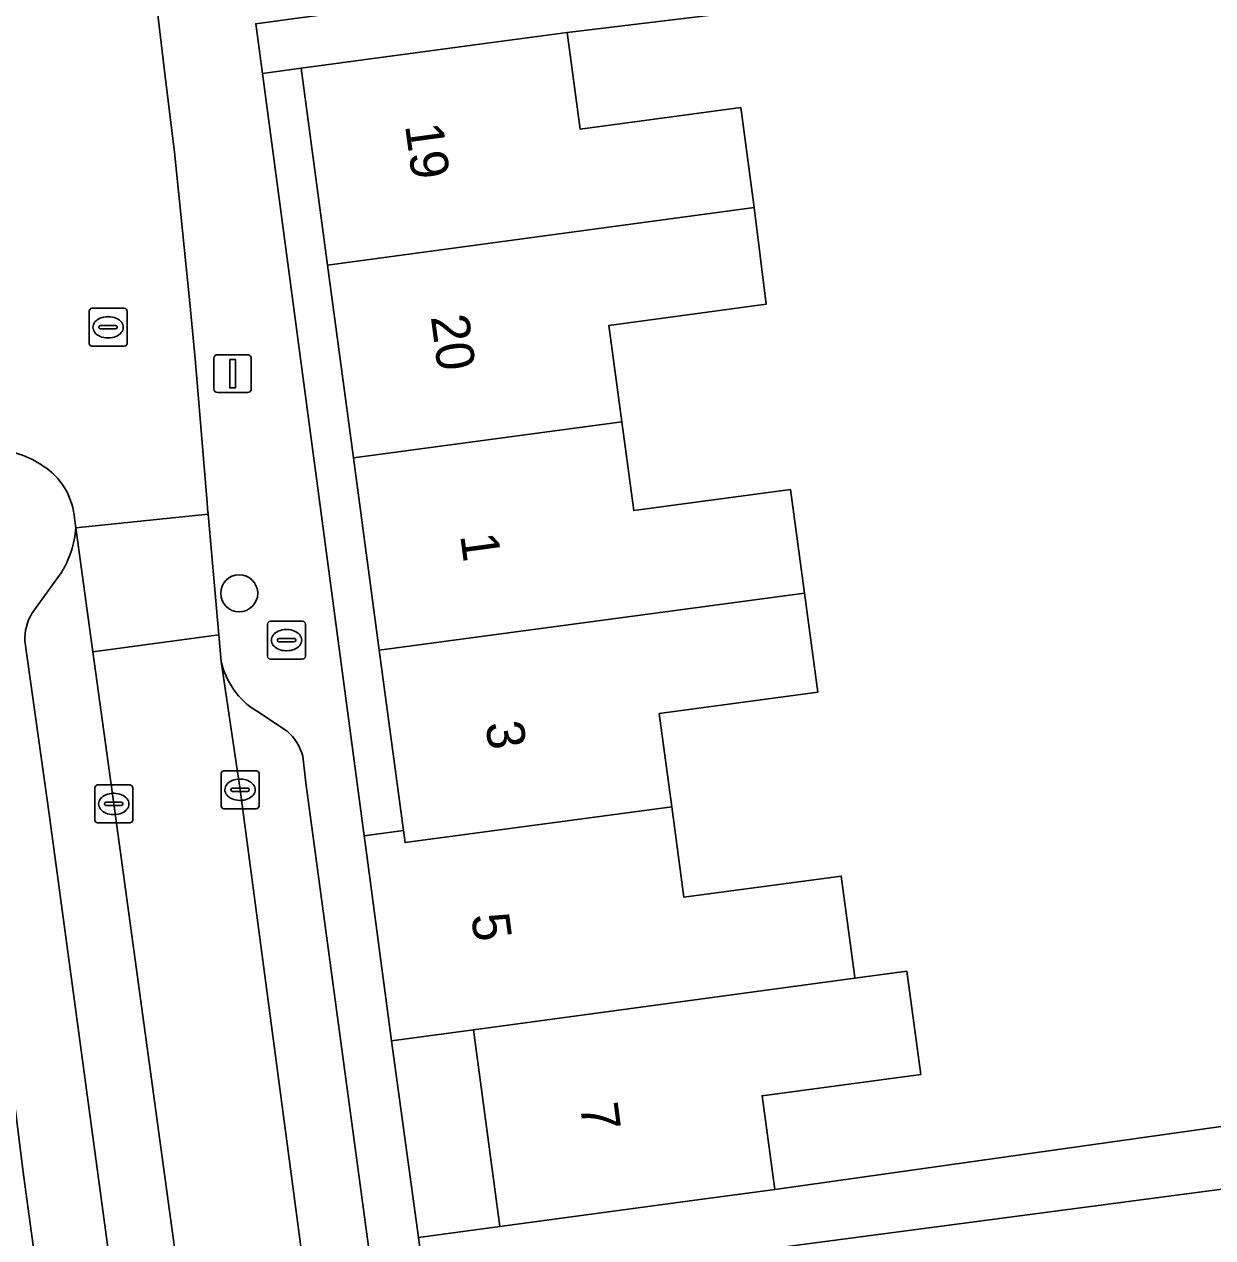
# Model space of a CAD drawing. Extents: x 163147 to 163550, y 380933 to 381639.
# Drawn here: x 163431.91 to 163463.29, y 381151.62 to 381183.65 of the extents above; entities that cross this region are included whole.
import ezdxf

# ---------------------------------------------------------------- set-up
doc = ezdxf.new("R2010")
doc.units = 0
for name, color, linetype in [('IMGEO_Boom', 7, 'Continuous'), ('IMGEO_Brandkraan', 7, 'Continuous'), ('IMGEO_Erf', 7, 'Continuous'), ('IMGEO_Kolk', 7, 'Continuous'), ('IMGEO_Lichtmast', 7, 'Continuous'), ('IMGEO_Pand', 7, 'Continuous'), ('IMGEO_Pand_nummerreeks', 7, 'Continuous'), ('IMGEO_Parkeervlak_open', 7, 'Continuous'), ('IMGEO_Rijbaan_lokaal_open', 7, 'Continuous'), ('IMGEO_Rioolput', 7, 'Continuous'), ('IMGEO_Voetpad_open', 7, 'Continuous')]:
    doc.layers.add(name, color=color, linetype=linetype)

msp = doc.modelspace()

# ---------------------------------------------------------------- linework, layer by layer
at = {"layer": 'IMGEO_Boom'}
msp.add_circle((163437.586, 381168.632), 0.489, dxfattribs=at)
at = {"layer": 'IMGEO_Brandkraan'}
for p, q in [((163438.335, 381166.969), (163438.335, 381167.821)), ((163438.41, 381167.895), (163439.262, 381167.895)), ((163438.823, 381167.675), (163438.848, 381167.675)), ((163439.336, 381167.821), (163439.336, 381166.969)), ((163438.594, 381167.389), (163438.594, 381167.401)), ((163439.032, 381167.352), (163438.634, 381167.352)), ((163438.637, 381167.438), (163439.035, 381167.438)), ((163439.078, 381167.401), (163439.078, 381167.389)), ((163438.846, 381167.115), (163438.821, 381167.115)), ((163439.262, 381166.895), (163438.41, 381166.895))]:
    msp.add_line(p, q, dxfattribs=at)
for points in [[(163438.335, 381166.969), (163438.335, 381167.821)], [(163438.41, 381167.895), (163439.262, 381167.895)], [(163439.336, 381167.821), (163439.336, 381166.969)], [(163439.262, 381166.895), (163438.41, 381166.895)]]:
    msp.add_lwpolyline(points, dxfattribs=at)
for centre, radius, start, end in [((163438.412, 381167.819), 0.0765, 91.552, 178.448), ((163438.412, 381167.819), 0.0765, 91.552, 178.448), ((163439.26, 381167.819), 0.0765, 1.552, 88.448), ((163439.26, 381167.819), 0.0765, 1.552, 88.448), ((163438.634, 381167.398), 0.0403, 85.8775, 175.7526), ((163438.631, 381167.388), 0.0366, 178.938, 274.7102), ((163439.035, 381167.395), 0.043, 264.8664, 352.4533), ((163439.039, 381167.4), 0.0386, 1.7309, 96.639), ((163438.412, 381166.971), 0.0765, 181.552, 268.448), ((163438.412, 381166.971), 0.0765, 181.552, 268.448), ((163439.26, 381166.971), 0.0765, 271.552, 358.448), ((163439.26, 381166.971), 0.0765, 271.552, 358.448)]:
    msp.add_arc(centre, radius, start, end, dxfattribs=at)
for centre, major_axis, ratio, start_param, end_param in [((163438.822, 381167.395), (-0.387, 0.002), 0.722429, 4.712389, 7.853982), ((163438.847, 381167.395), (-0.39, 0.002), 0.717154, 1.570796, 4.712389)]:
    msp.add_ellipse(centre, major_axis=major_axis, ratio=ratio, start_param=start_param, end_param=end_param, dxfattribs=at)
at = {"layer": 'IMGEO_Erf'}
for points in [[(163452.457, 381184.186), (163446.248, 381183.436), (163446.591, 381180.885), (163450.83, 381181.455), (163451.185, 381178.818), (163451.505, 381176.266), (163447.35, 381175.704), (163447.692, 381173.162), (163448.007, 381170.814), (163452.148, 381171.371), (163452.515, 381168.638), (163452.867, 381166.023), (163448.679, 381165.459), (163449.01, 381162.995), (163449.331, 381160.607), (163453.482, 381161.165), (163453.833, 381158.56), (163453.845, 381158.471), (163455.218, 381158.656), (163455.584, 381155.933), (163451.395, 381155.37), (163451.727, 381152.897), (163470.315, 381155.515)], [(163470.743, 381153.849), (163451.998, 381151.38)], [(163432.293, 381150.328), (163431.895, 381153.22)]]:
    msp.add_lwpolyline(points, dxfattribs=at)
for points in [[(163439.918, 381177.291), (163439.219, 381182.492), (163438.198, 381182.356), (163440.885, 381162.228), (163441.925, 381162.367), (163441.285, 381167.13), (163440.601, 381172.211)], [(163443.772, 381157.111), (163441.612, 381156.819), (163442.318, 381151.628), (163444.469, 381151.921)]]:
    msp.add_lwpolyline(points, close=True, dxfattribs=at)
at = {"layer": 'IMGEO_Kolk'}
for p, q in [((163437.108, 381163.02), (163437.108, 381163.872)), ((163437.183, 381163.946), (163438.035, 381163.946)), ((163438.109, 381163.872), (163438.109, 381163.02)), ((163433.773, 381162.646), (163433.773, 381163.498)), ((163433.848, 381163.572), (163434.7, 381163.572)), ((163434.774, 381163.498), (163434.774, 381162.646)), ((163437.41, 381163.489), (163437.808, 381163.489)), ((163437.596, 381163.726), (163437.621, 381163.726)), ((163434.261, 381163.352), (163434.286, 381163.352)), ((163437.367, 381163.44), (163437.367, 381163.452)), ((163437.805, 381163.403), (163437.407, 381163.403)), ((163437.619, 381163.166), (163437.594, 381163.166)), ((163437.851, 381163.452), (163437.851, 381163.44)), ((163434.032, 381163.066), (163434.032, 381163.078)), ((163434.47, 381163.029), (163434.072, 381163.029)), ((163434.075, 381163.115), (163434.473, 381163.115)), ((163434.516, 381163.078), (163434.516, 381163.066)), ((163438.035, 381162.946), (163437.183, 381162.946)), ((163434.7, 381162.572), (163433.848, 381162.572)), ((163434.284, 381162.792), (163434.259, 381162.792))]:
    msp.add_line(p, q, dxfattribs=at)
for points in [[(163437.108, 381163.02), (163437.108, 381163.872)], [(163437.183, 381163.946), (163438.035, 381163.946)], [(163438.109, 381163.872), (163438.109, 381163.02)], [(163433.773, 381162.646), (163433.773, 381163.498)], [(163433.848, 381163.572), (163434.7, 381163.572)], [(163434.774, 381163.498), (163434.774, 381162.646)], [(163438.035, 381162.946), (163437.183, 381162.946)], [(163434.7, 381162.572), (163433.848, 381162.572)]]:
    msp.add_lwpolyline(points, dxfattribs=at)
for centre, radius, start, end in [((163437.185, 381163.87), 0.0765, 91.552, 178.448), ((163437.185, 381163.87), 0.0765, 91.552, 178.448), ((163438.033, 381163.87), 0.0765, 1.552, 88.448), ((163438.033, 381163.87), 0.0765, 1.552, 88.448), ((163433.85, 381163.496), 0.0765, 91.552, 178.448), ((163433.85, 381163.496), 0.0765, 91.552, 178.448), ((163434.698, 381163.496), 0.0765, 1.552, 88.448), ((163434.698, 381163.496), 0.0765, 1.552, 88.448), ((163437.407, 381163.449), 0.0403, 85.8775, 175.7526), ((163437.812, 381163.451), 0.0386, 1.7309, 96.639), ((163437.404, 381163.439), 0.0366, 178.938, 274.7102), ((163437.808, 381163.446), 0.043, 264.8664, 352.4533), ((163434.072, 381163.075), 0.0403, 85.8775, 175.7526), ((163434.069, 381163.065), 0.0366, 178.938, 274.7102), ((163434.473, 381163.072), 0.043, 264.8664, 352.4533), ((163434.477, 381163.077), 0.0386, 1.7309, 96.639), ((163437.185, 381163.022), 0.0765, 181.552, 268.448), ((163437.185, 381163.022), 0.0765, 181.552, 268.448), ((163438.033, 381163.022), 0.0765, 271.552, 358.448), ((163438.033, 381163.022), 0.0765, 271.552, 358.448), ((163433.85, 381162.648), 0.0765, 181.552, 268.448), ((163433.85, 381162.648), 0.0765, 181.552, 268.448), ((163434.698, 381162.648), 0.0765, 271.552, 358.448), ((163434.698, 381162.648), 0.0765, 271.552, 358.448)]:
    msp.add_arc(centre, radius, start, end, dxfattribs=at)
for centre, major_axis, ratio, start_param, end_param in [((163437.595, 381163.446), (-0.387, 0.002), 0.722429, 4.712389, 7.853982), ((163437.62, 381163.446), (-0.39, 0.002), 0.717154, 1.570796, 4.712389), ((163434.26, 381163.072), (-0.387, 0.002), 0.722429, 4.712389, 7.853982), ((163434.285, 381163.072), (-0.39, 0.002), 0.717154, 1.570796, 4.712389)]:
    msp.add_ellipse(centre, major_axis=major_axis, ratio=ratio, start_param=start_param, end_param=end_param, dxfattribs=at)
at = {"layer": 'IMGEO_Lichtmast'}
for p, q in [((163436.916, 381174.03), (163436.916, 381174.83)), ((163436.916, 381174.83), (163436.916, 381174.03)), ((163437.016, 381174.93), (163437.806, 381174.93)), ((163437.806, 381174.93), (163437.016, 381174.93)), ((163437.906, 381174.83), (163437.906, 381174.03)), ((163437.906, 381174.03), (163437.906, 381174.83)), ((163437.806, 381173.93), (163437.016, 381173.93)), ((163437.016, 381173.93), (163437.806, 381173.93))]:
    msp.add_line(p, q, dxfattribs=at)
msp.add_lwpolyline([(163437.336, 381174.805), (163437.486, 381174.805), (163437.486, 381174.055), (163437.336, 381174.055), (163437.336, 381174.805)], dxfattribs=at)
for centre, start, end in [((163437.016, 381174.83), 90, 180), ((163437.016, 381174.83), 90, 180), ((163437.806, 381174.83), 0, 90), ((163437.806, 381174.83), 360, 90), ((163437.016, 381174.03), 180, 270), ((163437.016, 381174.03), 180, 270), ((163437.806, 381174.03), 270, 0), ((163437.806, 381174.03), 270, 0)]:
    msp.add_arc(centre, 0.1, start, end, dxfattribs=at)
at = {"layer": 'IMGEO_Pand'}
for points in [[(163439.918, 381177.291), (163451.185, 381178.818), (163450.83, 381181.455), (163446.591, 381180.885), (163446.248, 381183.436), (163444.133, 381183.152), (163439.219, 381182.492)], [(163447.692, 381173.162), (163447.35, 381175.704), (163451.505, 381176.266), (163451.185, 381178.818), (163439.918, 381177.291), (163440.601, 381172.211)], [(163447.692, 381173.162), (163440.601, 381172.211), (163441.285, 381167.13), (163452.515, 381168.638), (163452.148, 381171.371), (163448.007, 381170.814)], [(163448.679, 381165.459), (163452.867, 381166.023), (163452.515, 381168.638), (163441.285, 381167.13), (163441.925, 381162.367), (163441.968, 381162.05), (163449.01, 381162.995)], [(163453.482, 381161.165), (163449.331, 381160.607), (163449.01, 381162.995), (163441.968, 381162.05), (163441.925, 381162.367), (163440.885, 381162.228), (163440.928, 381161.91), (163441.612, 381156.819), (163443.772, 381157.111), (163453.845, 381158.471), (163453.833, 381158.56)], [(163451.395, 381155.37), (163455.584, 381155.933), (163455.218, 381158.656), (163453.845, 381158.471), (163443.772, 381157.111), (163444.469, 381151.921), (163449.425, 381152.587), (163451.727, 381152.897)]]:
    msp.add_lwpolyline(points, close=True, dxfattribs=at)
at = {"layer": 'IMGEO_Parkeervlak_open'}
for points in [[(163436.817, 381144.486), (163434.274, 381163.073), (163433.722, 381167.087), (163433.273, 381170.357)], [(163432.882, 381169.168), (163432.113, 381168.096)], [(163431.927, 381167.376), (163432.575, 381162.741), (163435.103, 381144.087), (163437.819, 381123.795), (163440.624, 381103.205), (163441.023, 381099.453)], [(163437.11, 381166.833), (163437.609, 381163.446), (163439.859, 381146.552), (163442.846, 381124.409), (163445.622, 381103.925), (163446.393, 381097.771), (163446.49, 381098.179)], [(163438.851, 381164.991), (163438.039, 381165.525)], [(163447.843, 381100.283), (163447.373, 381104.275), (163444.508, 381125.688), (163441.66, 381146.506), (163439.349, 381163.632), (163439.266, 381164.329)]]:
    msp.add_lwpolyline(points, dxfattribs=at)
for centre, radius, start, end in [((163430.575, 381170.585), 2.708, 328.4325, 355.1609), ((163433.172, 381167.438), 1.246, 148.1582, 182.8723), ((163439.161, 381167.306), 2.105, 192.9815, 237.7867), ((163437.976, 381163.982), 1.336, 15.0771, 49.0891)]:
    msp.add_arc(centre, radius, start, end, dxfattribs=at)
at = {"layer": 'IMGEO_Rijbaan_lokaal_open'}
for points in [[(163435.88, 381180.272), (163435.633, 381182.277), (163435.404, 381184.201), (163434.853, 381188.435), (163432.818, 381203.407), (163430.773, 381218.81), (163425.989, 381218.194), (163426.029, 381217.897), (163430.333, 381185.704), (163430.851, 381181.833)], [(163433.227, 381170.697), (163433.273, 381170.357), (163436.763, 381170.724), (163436.756, 381170.797), (163436.749, 381170.87), (163436.736, 381171.03), (163436.423, 381174.825), (163436.282, 381176.303), (163435.88, 381180.272)]]:
    msp.add_lwpolyline(points, dxfattribs=at)
for points in [[(163436.763, 381170.724), (163433.273, 381170.357), (163433.722, 381167.087), (163437.048, 381167.531)], [(163439.859, 381146.552), (163437.609, 381163.446), (163437.11, 381166.833), (163437.048, 381167.531), (163433.722, 381167.087), (163434.274, 381163.073), (163436.817, 381144.486), (163439.567, 381124.075), (163442.364, 381103.407), (163443.052, 381097.331), (163446.393, 381097.771), (163445.622, 381103.925), (163442.846, 381124.409)]]:
    msp.add_lwpolyline(points, close=True, dxfattribs=at)
for centre, radius, start, end in [((163431.094, 381170.142), 2.27, 54.4921, 90.4732), ((163431.429, 381170.467), 1.813, 7.2911, 57.1567)]:
    msp.add_arc(centre, radius, start, end, dxfattribs=at)
at = {"layer": 'IMGEO_Rioolput'}
for p, q in [((163433.624, 381175.228), (163433.624, 381176.08)), ((163433.699, 381176.154), (163434.551, 381176.154)), ((163434.625, 381176.08), (163434.625, 381175.228)), ((163433.883, 381175.648), (163433.883, 381175.66)), ((163433.926, 381175.697), (163434.324, 381175.697)), ((163434.112, 381175.934), (163434.137, 381175.934)), ((163434.367, 381175.66), (163434.367, 381175.648)), ((163434.321, 381175.611), (163433.923, 381175.611)), ((163434.135, 381175.374), (163434.11, 381175.374)), ((163434.551, 381175.154), (163433.699, 381175.154))]:
    msp.add_line(p, q, dxfattribs=at)
for points in [[(163433.624, 381175.228), (163433.624, 381176.08)], [(163433.699, 381176.154), (163434.551, 381176.154)], [(163434.625, 381176.08), (163434.625, 381175.228)], [(163434.551, 381175.154), (163433.699, 381175.154)]]:
    msp.add_lwpolyline(points, dxfattribs=at)
for centre, radius, start, end in [((163433.701, 381176.078), 0.0765, 91.552, 178.448), ((163433.701, 381176.078), 0.0765, 91.552, 178.448), ((163434.549, 381176.078), 0.0765, 1.552, 88.448), ((163434.549, 381176.078), 0.0765, 1.552, 88.448), ((163433.923, 381175.657), 0.0403, 85.8775, 175.7526), ((163433.92, 381175.647), 0.0366, 178.938, 274.7102), ((163434.324, 381175.654), 0.043, 264.8664, 352.4533), ((163434.328, 381175.659), 0.0386, 1.7309, 96.639), ((163433.701, 381175.23), 0.0765, 181.552, 268.448), ((163433.701, 381175.23), 0.0765, 181.552, 268.448), ((163434.549, 381175.23), 0.0765, 271.552, 358.448), ((163434.549, 381175.23), 0.0765, 271.552, 358.448)]:
    msp.add_arc(centre, radius, start, end, dxfattribs=at)
for centre, major_axis, ratio, start_param, end_param in [((163434.111, 381175.654), (-0.387, 0.002), 0.722429, 4.712389, 7.853982), ((163434.136, 381175.654), (-0.39, 0.002), 0.717154, 1.570796, 4.712389)]:
    msp.add_ellipse(centre, major_axis=major_axis, ratio=ratio, start_param=start_param, end_param=end_param, dxfattribs=at)
at = {"layer": 'IMGEO_Voetpad_open'}
for points in [[(163419.541, 381301.698), (163419.608, 381301.196), (163421.129, 381289.848), (163421.495, 381287.123), (163426.471, 381250), (163430.261, 381222.635), (163430.41, 381221.543), (163430.773, 381218.81), (163432.818, 381203.407), (163434.853, 381188.435), (163435.404, 381184.201), (163435.633, 381182.277), (163435.88, 381180.272), (163436.282, 381176.303), (163436.423, 381174.825), (163436.736, 381171.03), (163436.749, 381170.87), (163436.756, 381170.797), (163436.763, 381170.724), (163437.048, 381167.531), (163437.11, 381166.833)], [(163451.716, 381099.596), (163451.038, 381104.686), (163448.633, 381104.366), (163448.617, 381104.484), (163447.944, 381109.542), (163447.91, 381109.796), (163443.904, 381139.851), (163443.226, 381144.943), (163443.183, 381145.265), (163442.524, 381150.112), (163442.318, 381151.628), (163441.612, 381156.819), (163440.928, 381161.91), (163440.885, 381162.228), (163438.198, 381182.356), (163438.023, 381183.666)], [(163431.075, 381172.412), (163428.886, 381172.164), (163429.716, 381169.834), (163430.04, 381167.473), (163431.015, 381160.154), (163431.895, 381153.22), (163432.293, 381150.328), (163432.505, 381148.832), (163433.187, 381144.015), (163433.211, 381143.836), (163433.885, 381138.765), (163433.927, 381138.448), (163437.919, 381108.562), (163437.948, 381108.344), (163438.622, 381103.273), (163438.642, 381103.121), (163439.201, 381098.033), (163440.974, 381089.977)], [(163433.273, 381170.357), (163433.227, 381170.697)], [(163432.113, 381168.096), (163432.882, 381169.168)], [(163441.023, 381099.453), (163440.624, 381103.205), (163437.819, 381123.795), (163435.103, 381144.087), (163432.575, 381162.741), (163431.927, 381167.376)], [(163438.039, 381165.525), (163438.851, 381164.991)], [(163439.266, 381164.329), (163439.349, 381163.632), (163441.66, 381146.506), (163444.508, 381125.688), (163447.373, 381104.275), (163447.843, 381100.283)], [(163470.315, 381155.515), (163451.727, 381152.897), (163449.425, 381152.587), (163444.469, 381151.921), (163442.318, 381151.628), (163442.524, 381150.112), (163444.686, 381150.406), (163449.643, 381151.066), (163451.998, 381151.38), (163470.743, 381153.849)]]:
    msp.add_lwpolyline(points, dxfattribs=at)
msp.add_lwpolyline([(163451.409, 381185.441), (163446.073, 381184.742), (163444.015, 381184.467), (163439.059, 381183.804), (163438.023, 381183.666), (163438.198, 381182.356), (163439.219, 381182.492), (163444.133, 381183.152), (163446.248, 381183.436), (163452.457, 381184.186)], close=True, dxfattribs=at)
for centre, radius, start, end in [((163431.094, 381170.142), 2.27, 54.4921, 90.4732), ((163431.429, 381170.467), 1.813, 7.2911, 57.1567), ((163430.575, 381170.585), 2.708, 328.4325, 355.1609), ((163433.172, 381167.438), 1.246, 148.1582, 182.8723), ((163439.161, 381167.306), 2.105, 192.9815, 237.7867), ((163437.976, 381163.982), 1.336, 15.0771, 49.0891)]:
    msp.add_arc(centre, radius, start, end, dxfattribs=at)

# ---------------------------------------------------------------- texts
at = {"layer": 'IMGEO_Pand_nummerreeks'}
for s, rotation, p in [('19', 277.656, (163441.964, 381180.986)), ('20', 277.656, (163442.644, 381175.933)), ('1', 277.6601, (163443.419, 381170.166)), ('3', 277.6602, (163444.087, 381165.199)), ('5', 277.6545, (163443.71, 381160.133)), ('7', 277.6488, (163446.582, 381155.125))]:
    msp.add_text(s, height=1, rotation=rotation, dxfattribs=at).set_placement(p)

doc.saveas('drawing.dxf')
